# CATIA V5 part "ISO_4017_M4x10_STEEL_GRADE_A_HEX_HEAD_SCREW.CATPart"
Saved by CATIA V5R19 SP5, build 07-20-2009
Part number: ISO 4017 SCREW M4x10 STEEL GRADE A HEXAGON HEAD
Publications: "Mating Face", "Axis"
Bounding box of the stored display mesh (mm): x -10 to 2.925, y -3.5 to 3.5, z -4.041 to 4.041
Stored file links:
  Z:\UA\ATLAS\atlascar\ServoPiloto\dir\suportePotenciometro\V2\ISO_4017_M4x10_STEEL_GRADE_A_HEX_HEAD_SCREW.CATPart
  Z:\programs_vbox\Dassault Systemes\B19\intel_a\startup\components\MechanicalStandardParts\EN_Standards\Design_Tables\EN_ISO_4017_GRADES_A_B_HEXAGON_HEAD_SCREW.txt
  Z:\programs_vbox\Dassault Systemes\B19\intel_a\startup\components\MechanicalStandardParts\ISO_Standards\Design_Tables\ISO_4017_GRADES_A_B_HEXAGON_HEAD_SCREW.txt
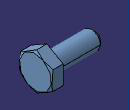
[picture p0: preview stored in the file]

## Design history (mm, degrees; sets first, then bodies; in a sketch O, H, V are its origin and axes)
Parameters
  Designation = "M4"
  d_dia = 4 mm
  l_length = 10 mm
  k_max_head_depth = 2.925 mm
  r_min = 0.2 mm
  s_nom_across_flats = 7 mm
  dw_min = 5.88 mm
  c_max = 0.4 mm
  P_pitch = 0.7 mm
  threading = 7.9 mm
Body1 "PartBody" (main body)
  Sketch1 on yz-plane, origin (0, 0, 0), H (0, 1, 0), V (0, 0, 1)
    circle A1 centre (0, 0) radius 2.94
    radius A1 = 2.94 {= dw_min /2}
  Pad1: profile Sketch1, direction (1, 0, 0), length 0.4 {= c_max}
  Sketch2 on face of Pad1, origin (0.4, 0, 0), H (0, 1, 0), V (0, 0, 1)
    point P1 (3.5, -2.0207)
    point P2 (3.5, 2.0207)
    point P3 (0, 4.0415)
    point P4 (-3.5, 2.0207)
    point P5 (-3.5, -2.0207)
    point P6 (0, -4.0415)
    point P7 (3.5, 0)
    line L1 (3.5, -2.0207) -> (3.5, 2.0207)
    line L2 (3.5, 2.0207) -> (0, 4.0415)
    line L3 (0, 4.0415) -> (-3.5, 2.0207)
    line L4 (-3.5, 2.0207) -> (-3.5, -2.0207)
    line L5 (-3.5, -2.0207) -> (0, -4.0415)
    line L6 (0, -4.0415) -> (3.5, -2.0207)
    construction line L7 (0, 0) -> (3.5, 0)
    construction circle A1 centre (0, 0) radius 4.0415
    construction arc A2 centre (-3.5, -2.0207) radius 4.0415 from (-3.5, 2.0207) to (0, -4.0415) cw
    construction arc A3 centre (3.5, 2.0207) radius 4.0415 from (0, 4.0415) to (3.5, -2.0207) ccw
    point P8 (-3.5, -2.0207)
    point P9 (3.5, 2.0207)
    distance L1 L4 = 7 {= s_nom_across_flats}
    horizontal: L7 H
    coincidence: A1 P1, A1 P2, A1 P3, A1 P4, A1 P5, A1 P6, A2 P4, A2 P6, A2 O, P8 P5, A3 P3, A3 P1, A3 O, P9 P2
    midpoint: P7 L1
  Pad2: profile Sketch2, direction (1, 0, 0), length 2.525 {= k_max_head_depth -c_max}
  Sketch3 on zx-plane, origin (0, 0, 0), H (-1, 0, 0), V (0, 0, 1)
    point P1 (-2.925, 3.4983)
    axis line L1 (-94.6904, 0) -> (76.7146, 0)
    reference intersected line E1 through (1000000, 0) direction (-1, 0) from xy-plane
    line L2 (-2.6114, 4.0415) -> (-2.925, 3.4983)
    line L3 (-2.6114, 4.0415) -> (-2.925, 4.0415)
    line L4 (-2.925, 4.0415) -> (-2.925, 3.4983)
    reference projected line E2 (-0.8, 4.0415) -> (-18.28, 4.0415) from edge [face of Pad2 | face of Pad2]
    distance P1 H = 3.4983 {= s_nom_across_flats /2.001}
    distance P1 V = 2.925 {= k_max_head_depth}
    angle L4 L2 = 30
    horizontal: L1 H, L3 H
    coincidence: L1 E1, L3 E2
    vertical: L4 V
  Groove1: profile Sketch3, axis Sketch3.L1, angle 360
  Sketch4 on face of Pad1, origin (0, 0, 0), H (0, -1, 0), V (0, 0, 1)
    circle A1 centre (0, 0) radius 1.9512
    radius A1 = 1.9512 {= d_dia /2.05}
  Pad3: profile Sketch4, direction (-1, 0, 0), length 10 {= l_length}
  Fillet1: radius 0.2 {= r_min}, on edge [face of Pad3 | face of Pad1]
  Chamfer1: length 0.7 {= P_pitch}, angle 45, on edge [face of Pad3 | face of Pad3]
  Thread1: diameter 3.9024 {= d_dia /1.025}, depth 7.9 {= threading}, pitch 1, on face of Pad3, from face of Pad3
